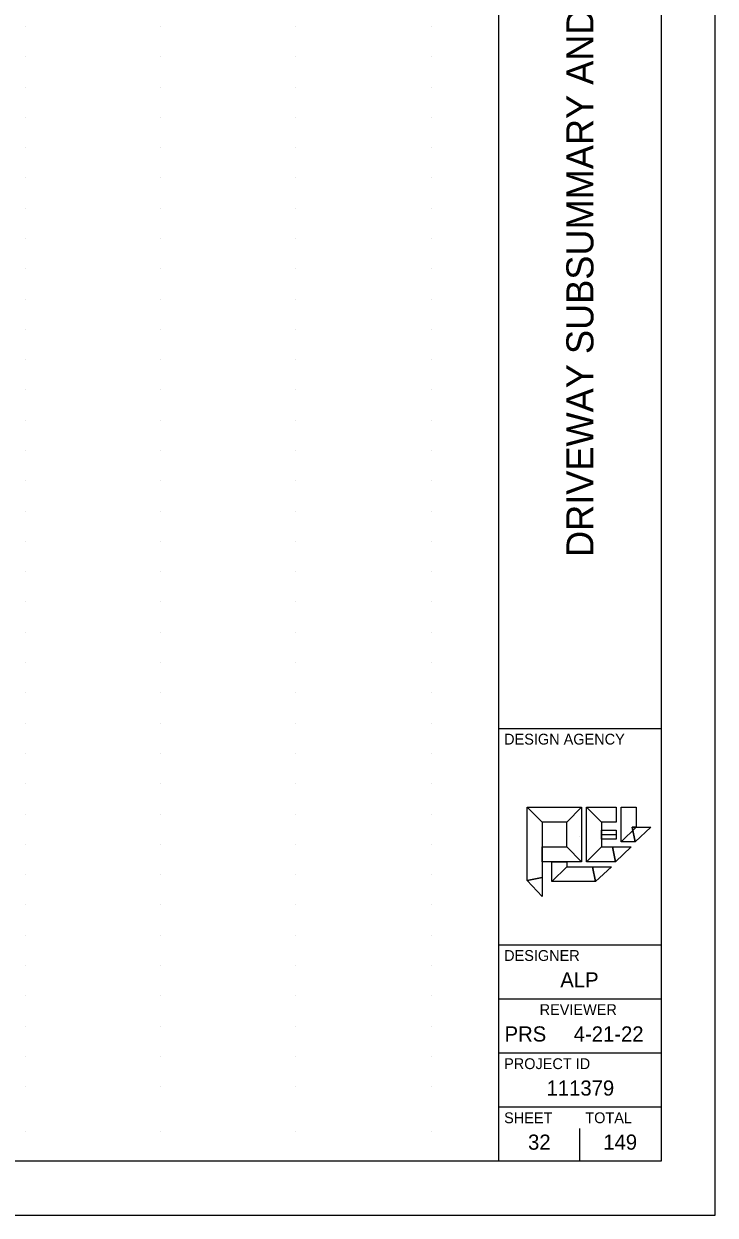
# Model space of a CAD drawing. Extents: x 2073163.9 to 2073197.9, y 634076.5 to 634098.5.
# Drawn here: x 2073191.56 to 2073197.95, y 634076.55 to 634087.56 of the extents above; entities that cross this region are included whole.
import ezdxf

# ---------------------------------------------------------------- set-up
doc = ezdxf.new("R2010")
doc.units = 0
for name, color, linetype in [('Default', 7, 'Continuous'), ('SH_Border', 7, 'Continuous'), ('SH_Cut_Line', 7, 'Continuous'), ('SH_Data', 7, 'Continuous')]:
    doc.layers.add(name, color=color, linetype=linetype)

msp = doc.modelspace()

# ---------------------------------------------------------------- linework, layer by layer
at = {"layer": 'Default'}
msp.add_line((2073196.896, 634080.068), (2073197.032, 634080.068), dxfattribs=at)
for points in [[(2073196.209, 634079.643), (2073196.209, 634080.32), (2073196.347, 634080.183), (2073196.347, 634079.671)], [(2073196.209, 634080.32), (2073196.712, 634080.32), (2073196.576, 634080.183), (2073196.347, 634080.183)], [(2073196.712, 634080.32), (2073196.712, 634079.817), (2073196.576, 634079.954), (2073196.576, 634080.183)], [(2073196.758, 634079.817), (2073196.758, 634080.32), (2073196.896, 634080.183), (2073196.896, 634079.954)], [(2073196.758, 634080.32), (2073197.032, 634080.32), (2073197.032, 634080.183), (2073196.896, 634080.183)], [(2073197.078, 634080), (2073197.078, 634080.32), (2073197.216, 634080.32), (2073197.216, 634080.137)], [(2073197.207, 634080), (2073197.078, 634080), (2073197.216, 634080.137), (2073197.179, 634080.137)], [(2073197.352, 634080.137), (2073197.207, 634080), (2073197.179, 634080.137)], [(2073197.032, 634080.11), (2073197.032, 634080.026), (2073196.897, 634080.026), (2073196.897, 634080.11)], [(2073196.712, 634079.817), (2073196.347, 634079.817), (2073196.347, 634079.954), (2073196.576, 634079.954)], [(2073197.024, 634079.817), (2073196.758, 634079.817), (2073196.896, 634079.954), (2073196.996, 634079.954)], [(2073197.169, 634079.954), (2073197.024, 634079.817), (2073196.996, 634079.954)], [(2073196.438, 634079.634), (2073196.438, 634079.817), (2073196.576, 634079.817), (2073196.576, 634079.771)], [(2073196.841, 634079.634), (2073196.438, 634079.634), (2073196.576, 634079.771), (2073196.812, 634079.771)], [(2073196.987, 634079.771), (2073196.841, 634079.634), (2073196.812, 634079.771)], [(2073196.347, 634079.497), (2073196.209, 634079.643), (2073196.347, 634079.671)]]:
    msp.add_lwpolyline(points, close=True, dxfattribs=at)
at = {"layer": 'SH_Border'}
for p, q in [((2073195.946, 634077.05), (2073195.946, 634098.05)), ((2073195.946, 634081.05), (2073197.446, 634081.05)), ((2073195.946, 634079.05), (2073197.446, 634079.05)), ((2073195.946, 634078.55), (2073197.446, 634078.55)), ((2073195.946, 634078.05), (2073197.446, 634078.05)), ((2073195.946, 634077.55), (2073197.446, 634077.55))]:
    msp.add_line(p, q, dxfattribs=at)
msp.add_lwpolyline([(2073165.446, 634098.05), (2073197.446, 634098.05), (2073197.446, 634077.05), (2073165.446, 634077.05)], close=True, dxfattribs=at)
at = {"layer": 'SH_Cut_Line'}
msp.add_lwpolyline([(2073163.946, 634076.55), (2073197.946, 634076.55), (2073197.946, 634098.55), (2073163.946, 634098.55)], close=True, dxfattribs=at)
at = {"layer": 'SH_Data'}
for p, q in [((2073191.571, 634087.538), (2073191.571, 634087.538)), ((2073192.821, 634087.538), (2073192.821, 634087.538)), ((2073194.071, 634087.538), (2073194.071, 634087.538)), ((2073195.321, 634087.538), (2073195.321, 634087.538)), ((2073191.571, 634087.258), (2073191.571, 634087.258)), ((2073192.821, 634087.258), (2073192.821, 634087.258)), ((2073194.071, 634087.258), (2073194.071, 634087.258)), ((2073195.321, 634087.258), (2073195.321, 634087.258)), ((2073191.571, 634086.978), (2073191.571, 634086.978)), ((2073192.821, 634086.978), (2073192.821, 634086.978)), ((2073194.071, 634086.978), (2073194.071, 634086.978)), ((2073195.321, 634086.978), (2073195.321, 634086.978)), ((2073191.571, 634086.698), (2073191.571, 634086.698)), ((2073192.821, 634086.698), (2073192.821, 634086.698)), ((2073194.071, 634086.698), (2073194.071, 634086.698)), ((2073195.321, 634086.698), (2073195.321, 634086.698)), ((2073191.571, 634086.418), (2073191.571, 634086.418)), ((2073192.821, 634086.418), (2073192.821, 634086.418)), ((2073194.071, 634086.418), (2073194.071, 634086.418)), ((2073195.321, 634086.418), (2073195.321, 634086.418)), ((2073191.571, 634086.138), (2073191.571, 634086.138)), ((2073192.821, 634086.138), (2073192.821, 634086.138)), ((2073194.071, 634086.138), (2073194.071, 634086.138)), ((2073195.321, 634086.138), (2073195.321, 634086.138)), ((2073191.571, 634085.858), (2073191.571, 634085.858)), ((2073192.821, 634085.858), (2073192.821, 634085.858)), ((2073194.071, 634085.858), (2073194.071, 634085.858)), ((2073195.321, 634085.858), (2073195.321, 634085.858)), ((2073191.571, 634085.578), (2073191.571, 634085.578)), ((2073192.821, 634085.578), (2073192.821, 634085.578)), ((2073194.071, 634085.578), (2073194.071, 634085.578)), ((2073195.321, 634085.578), (2073195.321, 634085.578)), ((2073191.571, 634085.298), (2073191.571, 634085.298)), ((2073192.821, 634085.298), (2073192.821, 634085.298)), ((2073194.071, 634085.298), (2073194.071, 634085.298)), ((2073195.321, 634085.298), (2073195.321, 634085.298)), ((2073191.571, 634085.018), (2073191.571, 634085.018)), ((2073192.821, 634085.018), (2073192.821, 634085.018)), ((2073194.071, 634085.018), (2073194.071, 634085.018)), ((2073195.321, 634085.018), (2073195.321, 634085.018)), ((2073191.571, 634084.738), (2073191.571, 634084.738)), ((2073192.821, 634084.738), (2073192.821, 634084.738)), ((2073194.071, 634084.738), (2073194.071, 634084.738)), ((2073195.321, 634084.738), (2073195.321, 634084.738)), ((2073191.571, 634084.458), (2073191.571, 634084.458)), ((2073192.821, 634084.458), (2073192.821, 634084.458)), ((2073194.071, 634084.458), (2073194.071, 634084.458)), ((2073195.321, 634084.458), (2073195.321, 634084.458)), ((2073191.571, 634084.178), (2073191.571, 634084.178)), ((2073192.821, 634084.178), (2073192.821, 634084.178)), ((2073194.071, 634084.178), (2073194.071, 634084.178)), ((2073195.321, 634084.178), (2073195.321, 634084.178)), ((2073191.571, 634083.898), (2073191.571, 634083.898)), ((2073192.821, 634083.898), (2073192.821, 634083.898)), ((2073194.071, 634083.898), (2073194.071, 634083.898)), ((2073195.321, 634083.898), (2073195.321, 634083.898)), ((2073191.571, 634083.618), (2073191.571, 634083.618)), ((2073192.821, 634083.618), (2073192.821, 634083.618)), ((2073194.071, 634083.618), (2073194.071, 634083.618)), ((2073195.321, 634083.618), (2073195.321, 634083.618)), ((2073191.571, 634083.338), (2073191.571, 634083.338)), ((2073192.821, 634083.338), (2073192.821, 634083.338)), ((2073194.071, 634083.338), (2073194.071, 634083.338)), ((2073195.321, 634083.338), (2073195.321, 634083.338)), ((2073191.571, 634083.058), (2073191.571, 634083.058)), ((2073192.821, 634083.058), (2073192.821, 634083.058)), ((2073194.071, 634083.058), (2073194.071, 634083.058)), ((2073195.321, 634083.058), (2073195.321, 634083.058)), ((2073191.571, 634082.778), (2073191.571, 634082.778)), ((2073192.821, 634082.778), (2073192.821, 634082.778)), ((2073194.071, 634082.778), (2073194.071, 634082.778)), ((2073195.321, 634082.778), (2073195.321, 634082.778)), ((2073191.571, 634082.498), (2073191.571, 634082.498)), ((2073192.821, 634082.498), (2073192.821, 634082.498)), ((2073194.071, 634082.498), (2073194.071, 634082.498)), ((2073195.321, 634082.498), (2073195.321, 634082.498)), ((2073191.571, 634082.218), (2073191.571, 634082.218)), ((2073192.821, 634082.218), (2073192.821, 634082.218)), ((2073194.071, 634082.218), (2073194.071, 634082.218)), ((2073195.321, 634082.218), (2073195.321, 634082.218)), ((2073191.571, 634081.938), (2073191.571, 634081.938)), ((2073192.821, 634081.938), (2073192.821, 634081.938)), ((2073194.071, 634081.938), (2073194.071, 634081.938)), ((2073195.321, 634081.938), (2073195.321, 634081.938)), ((2073191.571, 634081.658), (2073191.571, 634081.658)), ((2073192.821, 634081.658), (2073192.821, 634081.658)), ((2073194.071, 634081.658), (2073194.071, 634081.658)), ((2073195.321, 634081.658), (2073195.321, 634081.658)), ((2073191.571, 634081.378), (2073191.571, 634081.378)), ((2073192.821, 634081.378), (2073192.821, 634081.378)), ((2073194.071, 634081.378), (2073194.071, 634081.378)), ((2073195.321, 634081.378), (2073195.321, 634081.378)), ((2073191.571, 634081.098), (2073191.571, 634081.098)), ((2073192.821, 634081.098), (2073192.821, 634081.098)), ((2073194.071, 634081.098), (2073194.071, 634081.098)), ((2073195.321, 634081.098), (2073195.321, 634081.098)), ((2073191.571, 634080.818), (2073191.571, 634080.818)), ((2073192.821, 634080.818), (2073192.821, 634080.818)), ((2073194.071, 634080.818), (2073194.071, 634080.818)), ((2073195.321, 634080.818), (2073195.321, 634080.818)), ((2073191.571, 634080.538), (2073191.571, 634080.538)), ((2073192.821, 634080.538), (2073192.821, 634080.538)), ((2073194.071, 634080.538), (2073194.071, 634080.538)), ((2073195.321, 634080.538), (2073195.321, 634080.538)), ((2073191.571, 634080.258), (2073191.571, 634080.258)), ((2073192.821, 634080.258), (2073192.821, 634080.258)), ((2073194.071, 634080.258), (2073194.071, 634080.258)), ((2073195.321, 634080.258), (2073195.321, 634080.258)), ((2073196.696, 634080.05), (2073196.696, 634080.05)), ((2073191.571, 634079.978), (2073191.571, 634079.978)), ((2073192.821, 634079.978), (2073192.821, 634079.978)), ((2073194.071, 634079.978), (2073194.071, 634079.978)), ((2073195.321, 634079.978), (2073195.321, 634079.978)), ((2073191.571, 634079.698), (2073191.571, 634079.698)), ((2073192.821, 634079.698), (2073192.821, 634079.698)), ((2073194.071, 634079.698), (2073194.071, 634079.698)), ((2073195.321, 634079.698), (2073195.321, 634079.698)), ((2073191.571, 634079.418), (2073191.571, 634079.418)), ((2073192.821, 634079.418), (2073192.821, 634079.418)), ((2073194.071, 634079.418), (2073194.071, 634079.418)), ((2073195.321, 634079.418), (2073195.321, 634079.418)), ((2073191.571, 634079.138), (2073191.571, 634079.138)), ((2073192.821, 634079.138), (2073192.821, 634079.138)), ((2073194.071, 634079.138), (2073194.071, 634079.138)), ((2073195.321, 634079.138), (2073195.321, 634079.138)), ((2073191.571, 634078.858), (2073191.571, 634078.858)), ((2073192.821, 634078.858), (2073192.821, 634078.858)), ((2073194.071, 634078.858), (2073194.071, 634078.858)), ((2073195.321, 634078.858), (2073195.321, 634078.858)), ((2073191.571, 634078.578), (2073191.571, 634078.578)), ((2073192.821, 634078.578), (2073192.821, 634078.578)), ((2073194.071, 634078.578), (2073194.071, 634078.578)), ((2073195.321, 634078.578), (2073195.321, 634078.578)), ((2073191.571, 634078.298), (2073191.571, 634078.298)), ((2073192.821, 634078.298), (2073192.821, 634078.298)), ((2073194.071, 634078.298), (2073194.071, 634078.298)), ((2073195.321, 634078.298), (2073195.321, 634078.298)), ((2073191.571, 634078.018), (2073191.571, 634078.018)), ((2073192.821, 634078.018), (2073192.821, 634078.018)), ((2073194.071, 634078.018), (2073194.071, 634078.018)), ((2073195.321, 634078.018), (2073195.321, 634078.018)), ((2073191.571, 634077.738), (2073191.571, 634077.738)), ((2073192.821, 634077.738), (2073192.821, 634077.738)), ((2073194.071, 634077.738), (2073194.071, 634077.738)), ((2073195.321, 634077.738), (2073195.321, 634077.738)), ((2073191.571, 634077.324), (2073191.571, 634077.324)), ((2073192.821, 634077.324), (2073192.821, 634077.324)), ((2073194.071, 634077.324), (2073194.071, 634077.324)), ((2073195.321, 634077.324), (2073195.321, 634077.324)), ((2073196.696, 634077.05), (2073196.696, 634077.35)), ((2073196.321, 634077.225), (2073196.321, 634077.225))]:
    msp.add_line(p, q, dxfattribs=at)

# ---------------------------------------------------------------- texts
msp.add_text('DRIVEWAY SUBSUMMARY AND ADDITIONAL EARTHWORK - CR 180 SUBSUMMARY', height=0.25, rotation=90, dxfattribs=at).set_placement((2073196.821, 634082.634))
for s, height, p in [('DESIGN AGENCY', 0.1, (2073195.996, 634080.9)), ('DESIGNER', 0.1, (2073195.996, 634078.9)), ('ALP', 0.14, (2073196.515, 634078.655)), ('REVIEWER', 0.1, (2073196.324, 634078.4)), ('PRS', 0.14, (2073196, 634078.155)), ('4-21-22', 0.14, (2073196.639, 634078.155)), ('PROJECT ID', 0.1, (2073195.996, 634077.9)), ('111379', 0.14, (2073196.388, 634077.655)), ('SHEET', 0.1, (2073195.996, 634077.4)), ('TOTAL', 0.1, (2073196.746, 634077.4)), ('32', 0.14, (2073196.217, 634077.155)), ('149', 0.14, (2073196.912, 634077.155))]:
    msp.add_text(s, height=height, dxfattribs=at).set_placement(p)

doc.saveas('drawing.dxf')
